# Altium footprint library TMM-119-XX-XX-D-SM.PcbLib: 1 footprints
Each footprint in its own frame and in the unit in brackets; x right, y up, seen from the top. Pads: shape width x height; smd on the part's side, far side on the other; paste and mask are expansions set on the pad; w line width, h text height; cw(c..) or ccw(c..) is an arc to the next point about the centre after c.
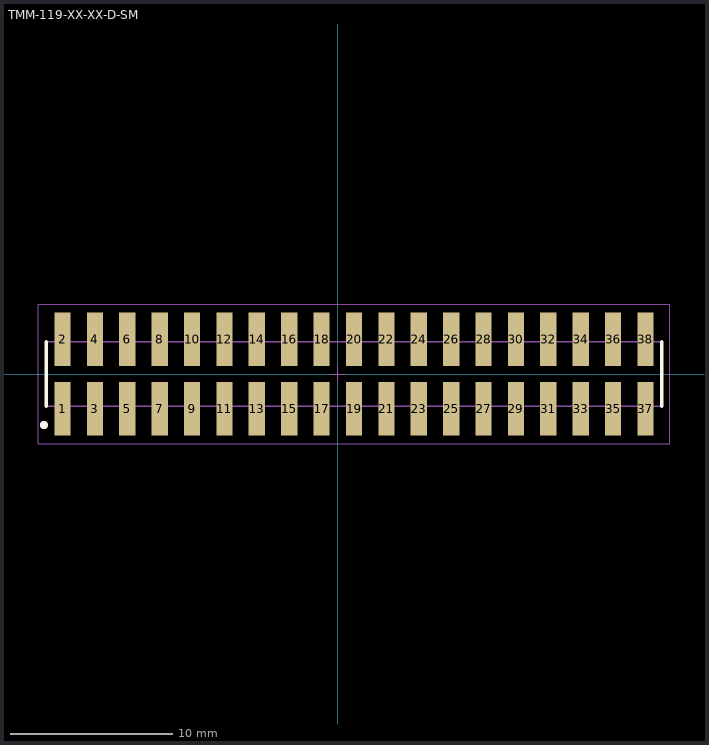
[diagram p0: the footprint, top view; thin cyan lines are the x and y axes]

## TMM-119-XX-XX-D-SM [mm] "2.00mm pitch, 38 pin, terminal strip; double row, SMT"
height 2.77
pads (38):
  rect 1x3.3 smd mask+0: 1(-17,-2.15) 2(-17,2.15) 3(-15,-2.15) 4(-15,2.15) 5(-13,-2.15) 6(-13,2.15) 7(-11,-2.15) 8(-11,2.15) 9(-9,-2.15) 10(-9,2.15) 11(-7,-2.15) 12(-7,2.15) 13(-5,-2.15) 14(-5,2.15) 15(-3,-2.15) 16(-3,2.15) 17(-1,-2.15) 18(-1,2.15) 19(1,-2.15) 20(1,2.15) 21(3,-2.15) 22(3,2.15) 23(5,-2.15) 24(5,2.15) 25(7,-2.15) 26(7,2.15) 27(9,-2.15) 28(9,2.15) 29(11,-2.15) 30(11,2.15) 31(13,-2.15) 32(13,2.15) 33(15,-2.15) 34(15,2.15) 35(17,-2.15) 36(17,2.15) 37(19,-2.15) 38(19,2.15)
Top Overlay:
  circle w0.25: c-18.15,-3.15 r0.125
  lines w0.2: -18,-2 -18,2 ; 20,-2 20,2
Mechanical 12:
  lines w0.001: -18,-2 -18,2 20,2 20,-2 -18,-2
Mechanical 13:
  lines w0.1: -18,-2 -18,2 20,2 20,-2 -18,-2
  text ".Designator" at 0,-0.127 h1.52
Mechanical 15:
  lines w0.05: -0.5,0 0.5,0 ; 0,-0.5 0,0.5 ; -18.5,-4.3 -18.5,4.3 20.5,4.3 20.5,-4.3 -18.5,-4.3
